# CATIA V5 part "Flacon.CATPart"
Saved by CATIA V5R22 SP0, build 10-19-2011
Part number: Flacon
Material "Vert": density 7860 kg/m3, Young's modulus 2e+11 Pa, Poisson ratio 0.266
Bounding box of the stored display mesh (mm): x -25 to 25, y -25 to 25, z 0 to 50
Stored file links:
  C:\Users\La forge\Desktop\CAO_PER_pick&place_2023A\Sous_Ensemble_Flacon\Flacon.CATPart
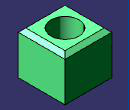
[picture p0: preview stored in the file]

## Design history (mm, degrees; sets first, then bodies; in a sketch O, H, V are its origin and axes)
Body1 (main body), material "Vert"
  Sketch1 on xy-plane, origin (0, 0, 0), H (1, 0, 0), V (0, 1, 0)
    line L1 (25, 25) -> (25, -25)
    line L2 (25, -25) -> (-25, -25)
    line L3 (-25, -25) -> (-25, 25)
    line L4 (-25, 25) -> (25, 25)
    length L1 = 50
    length L2 = 50
    vertical: L1 V, L3 V
    horizontal: L2 H, L4 H
    equidistance: L1 L3 O, L2 L4 O
  Pad1: profile Sketch1, direction (0, 0, 1), length 50
  Sketch2 on end face of Pad1, origin (5.616, -5.616, 50), H (1, 0, 0), V (0, 1, 0)
    point P1 (-5.616, 5.616)
    reference projected line E1 (19.384, -19.384) -> (19.384, 30.616) from edge [face of Pad1 from Sketch1.L1 | end face of Pad1]
    reference projected line E2 (-30.616, -19.384) -> (19.384, -19.384) from edge [face of Pad1 from Sketch1.L2 | end face of Pad1]
    distance P1 E1 = 25
    distance P1 E2 = 25
  Hole1: placed by Sketch2, at (0, 0, 50) direction (0, 0, -1), diameter 30, depth 40
  Chamfer1: length 4, angle 45, on edge [face of Pad1 from Sketch1.L4 | end face of Pad1]; edge [face of Pad1 from Sketch1.L3 | end face of Pad1]; edge [face of Pad1 from Sketch1.L2 | end face of Pad1]; edge [face of Pad1 from Sketch1.L1 | end face of Pad1]; edge [start face of Pad1 | face of Pad1 from Sketch1.L3]; edge [start face of Pad1 | face of Pad1 from Sketch1.L4]; edge [start face of Pad1 | face of Pad1 from Sketch1.L2]; edge [start face of Pad1 | face of Pad1 from Sketch1.L1]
